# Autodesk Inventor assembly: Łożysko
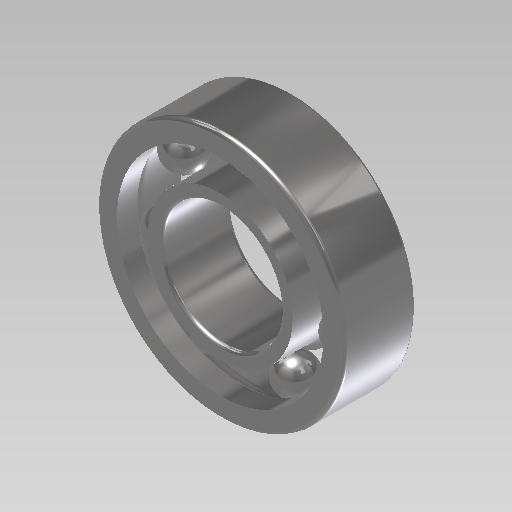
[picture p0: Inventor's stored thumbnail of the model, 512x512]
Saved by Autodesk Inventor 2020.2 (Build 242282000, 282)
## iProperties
Created: 2014-10
Part Number: Łożysko
Document SubType Name: Assembly
Designer: F.Stasiak
Catalog Web Link: www.expertbooks.pl
ClientObjectVersion: 1
Manager: www.cadconsulting.pl
Company: Fabian Stasiak CAD Consulting
Author: F.Stasiak
Subject: Zbiór ćwiczeń. Autodesk Inventor 2020. Kurs Professional
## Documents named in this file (2)
- C:\2020_Kurs_Professional\R3 Dynamika\AIR_100\Design Accelerator\Łożysko2.iam
- C:\2020_Kurs_Professional\Zasoby\ContentCenter\pl-PL\DIN 628 SKF(4)\DIN 628 SKF - SKF 7205 BE.ipt
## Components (1 placed, 1 different names)
1. DIN 628 SKF SKF 7205 BE:1
